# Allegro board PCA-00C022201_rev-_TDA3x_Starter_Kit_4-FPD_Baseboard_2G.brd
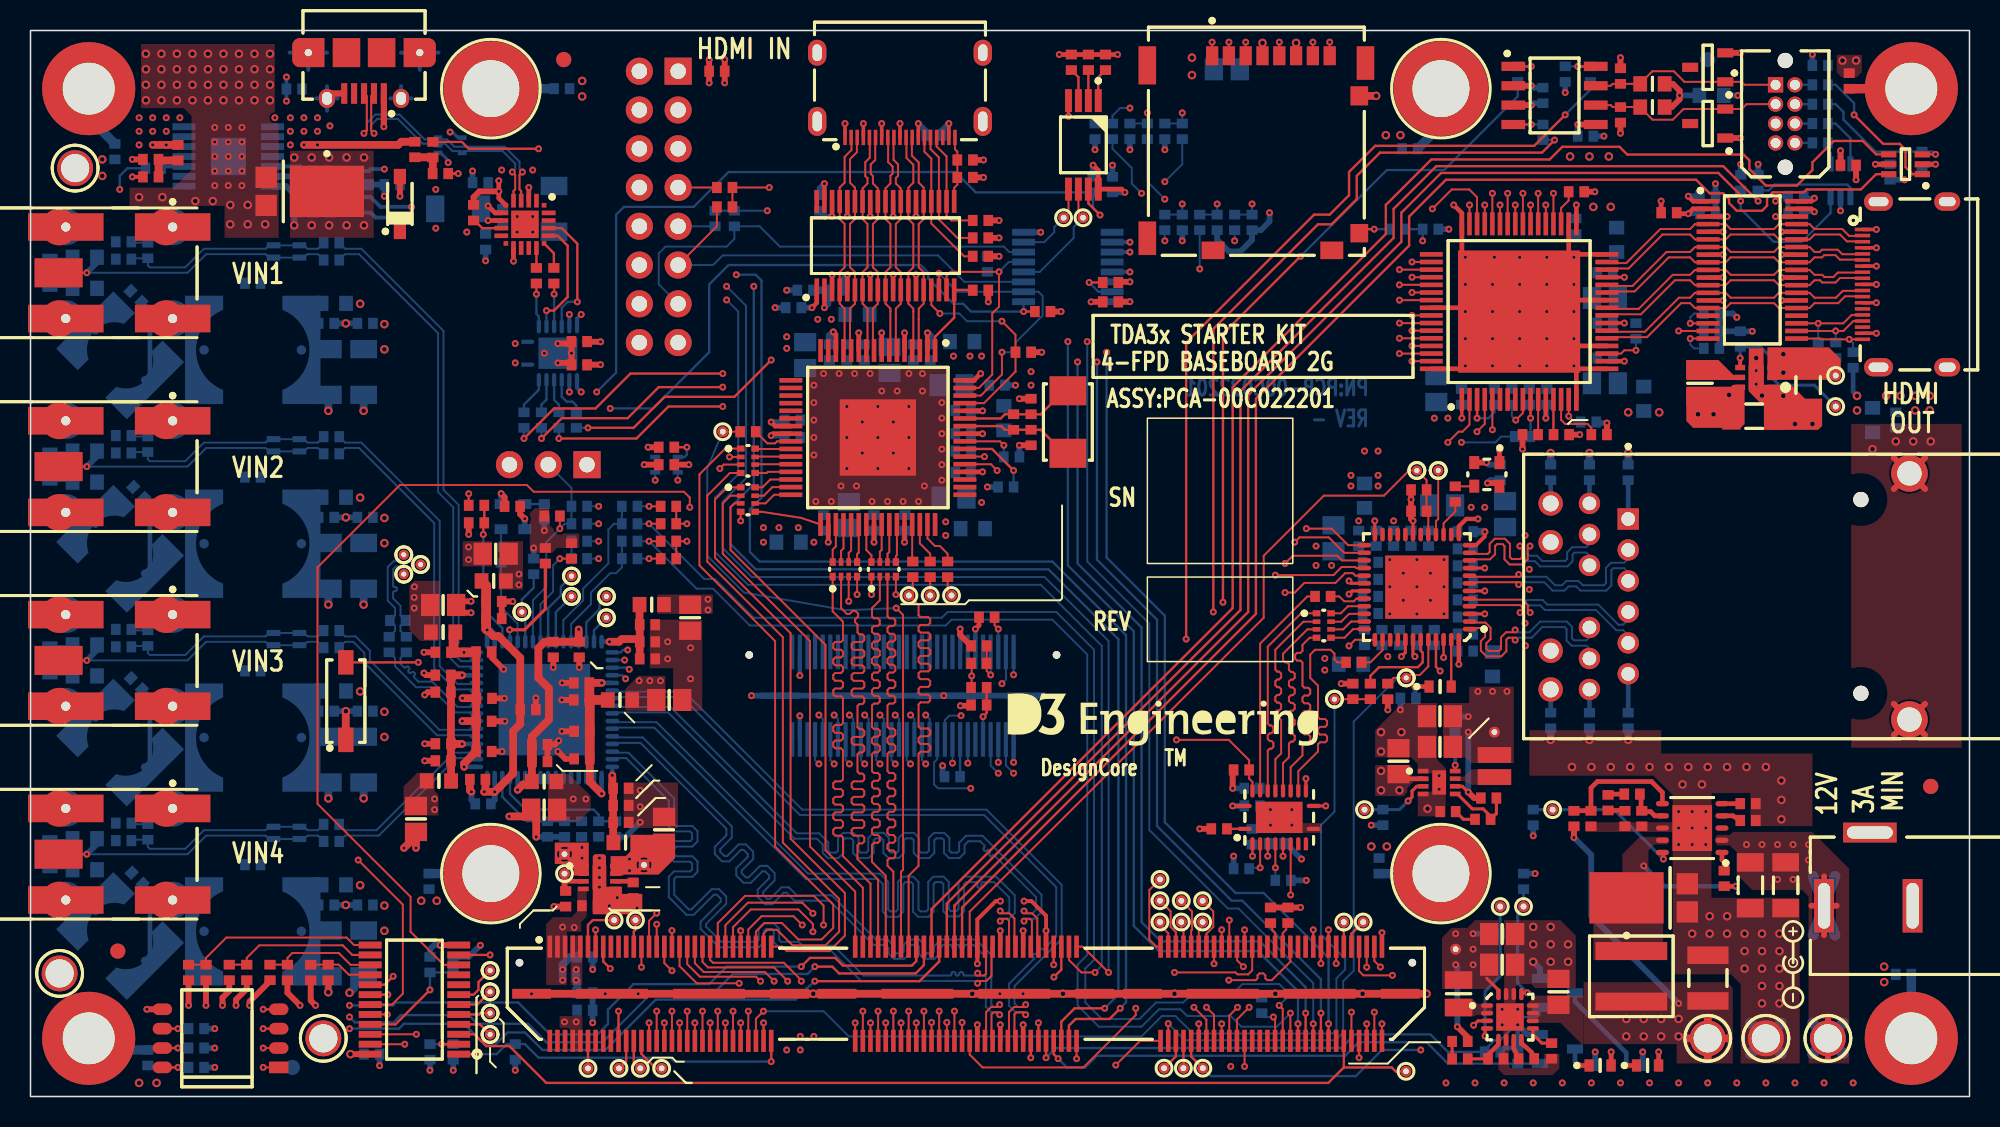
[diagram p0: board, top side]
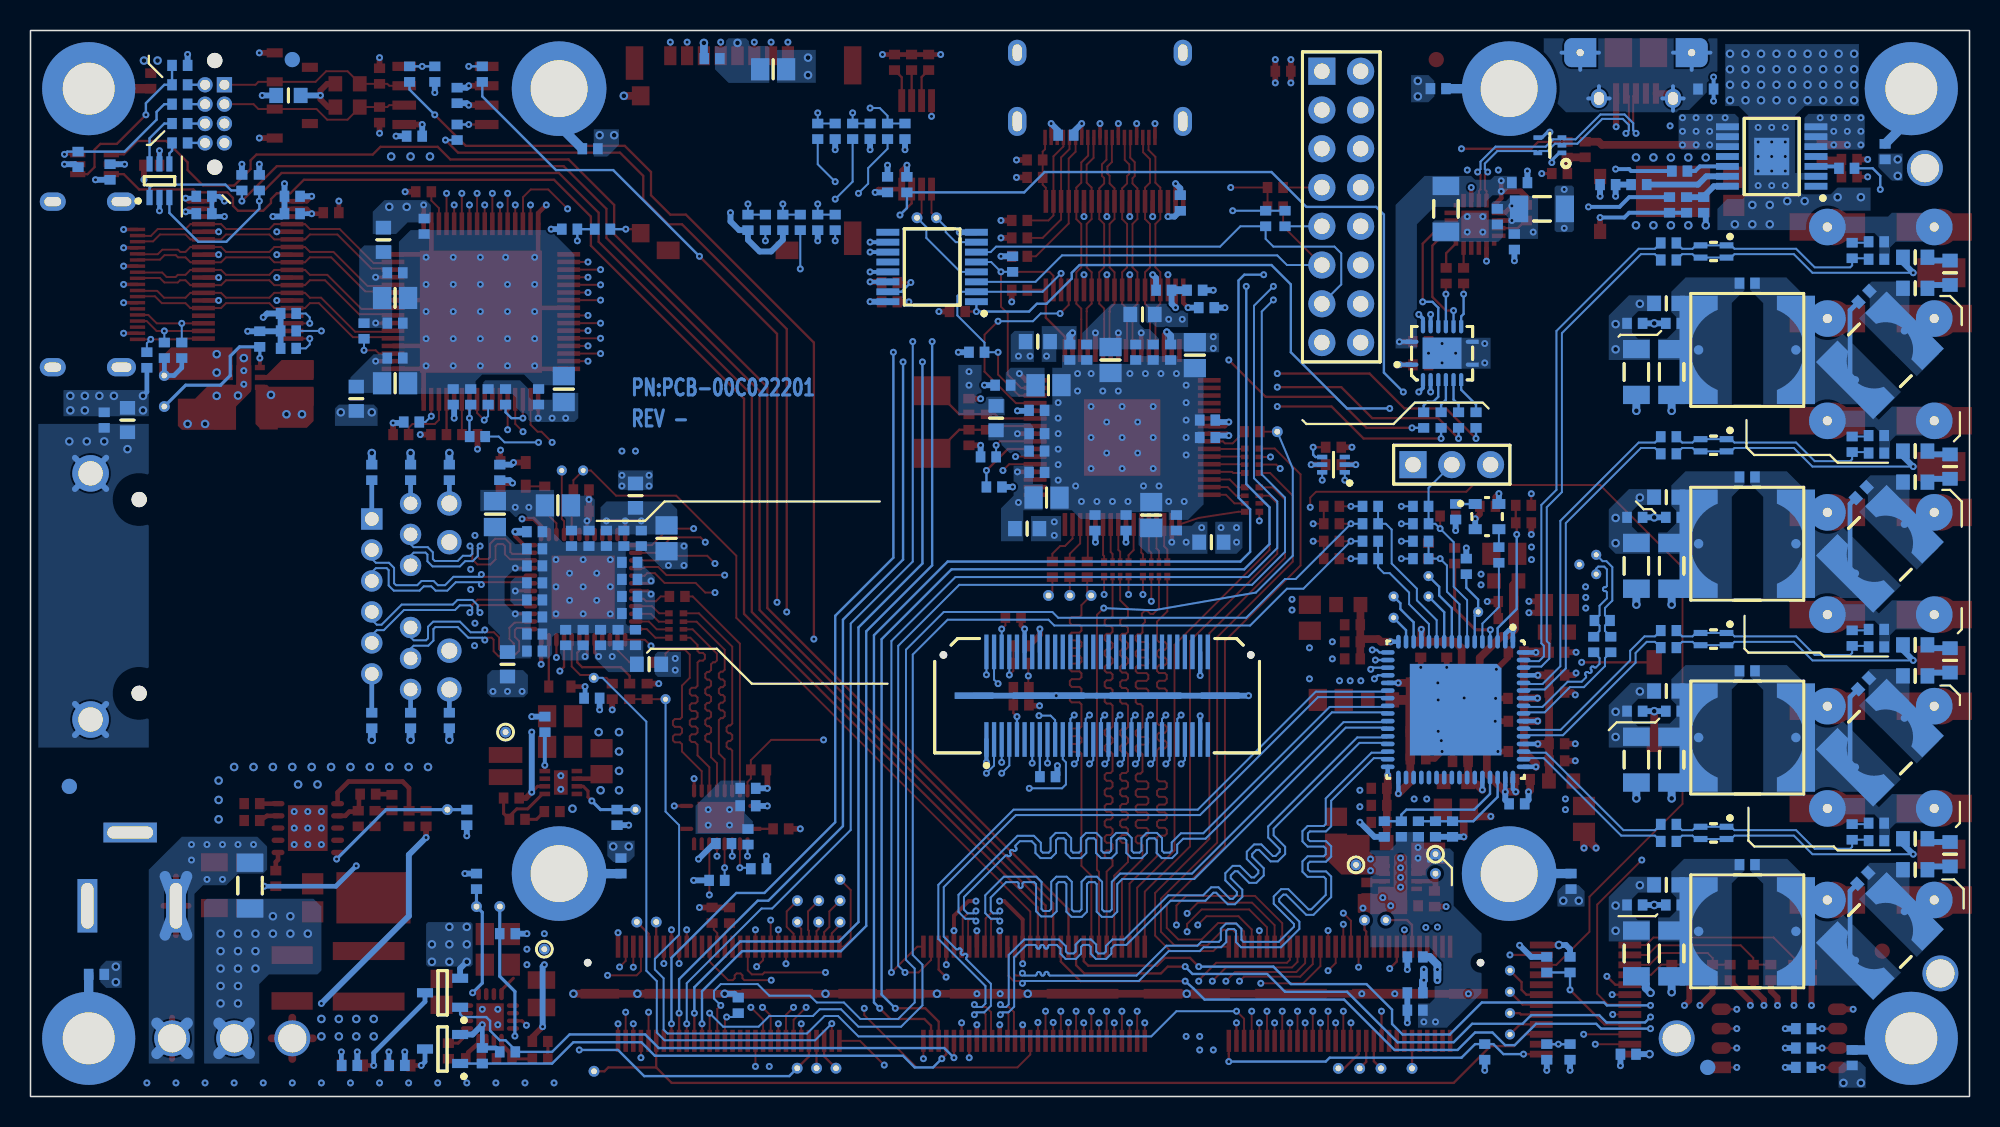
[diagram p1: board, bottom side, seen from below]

Outline 127 x 69.85 mm; copper layers: TOP, GND1, INNER1, GND2, PWR1, PWR2, GND3, INNER2, GND4, BOTTOM. Coordinates in mm from the lower left corner of the outline.
Outline path: rectangle 0,0 127,69.85

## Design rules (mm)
constraint set DEFAULT: min track width 0.152
net group CSI2_0_0: nets CSI2_0_DX0 CSI2_0_DY0
net group CSI2_0_1: nets CSI2_0_DX1 CSI2_0_DY1
net group CSI2_0_2: nets CSI2_0_DX2 CSI2_0_DY2
net group CSI2_0_3: nets CSI2_0_DX3 CSI2_0_DY3
net group CSI2_0_4: nets CSI2_0_DX4 CSI2_0_DY4
net group DCAN1: nets DCAN1_H DCAN1_L
net group HDMI_IN_CLK: nets HDMI_IN_CLKN HDMI_IN_CLKP
net group HDMI_IN_D0: nets HDMI_IN_D0N HDMI_IN_D0P
net group HDMI_IN_D1: nets HDMI_IN_D1N HDMI_IN_D1P
net group HDMI_IN_D2: nets HDMI_IN_D2N HDMI_IN_D2P
net group LPTX: nets LPTXN LPTXP
net group LPTX_C: nets LPTX_C_N LPTX_C_P
net group RIN0: nets RIN0_N RIN0_P
net group RIN0_C: nets RIN0_C_N RIN0_C_P
net group RIN1: nets RIN1_N RIN1_P
net group RIN1_C: nets RIN1_C_N RIN1_C_P
net group RIN2: nets RIN2_N RIN2_P
net group RIN2_C: nets RIN2_C_N RIN2_C_P
net group RIN3: nets RIN3_N RIN3_P
net group RIN3_C: nets RIN3_C_N RIN3_C_P
net group TD_A: nets TD_A_N TD_A_P
net group TD_B: nets TD_B_N TD_B_P
net group TD_C: nets TD_C_N TD_C_P
net group TD_D: nets TD_D_N TD_D_P
net group TXC: nets TXC_N TXC_P
net group TXD0: nets TXD0_N TXD0_P
net group TXD1: nets TXD1_N TXD1_P
net group TXD2: nets TXD2_N TXD2_P
net group USB_D: nets USB_DM USB_DP

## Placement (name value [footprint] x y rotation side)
C1  0.1uF  [CAPCEIA0402]  110.93 14.29 270 top
C2  10uF  [CAPCEIA1206]  112.65 13.84 270 top
C3  47uF  [CAPCEIA1210]  109.87 7.76 90 top
C5  2700pF  [CAPCEIA0402]  112.5 18.08 0 top
C6  12pF  [CAPCEIA0402]  105.54 18.21 270 top
C7  2700pF  [CAPCEIA0402]  104.43 18.21 270 top
C20  4.7uF  [CAPCEIA1206]  116.43 46.61 270 top
C21  4.7uF  [CAPCEIA1206]  112.9 44.58 0 top
C22  0.01uF  [CAPCEIA0402]  97.98 2.48 180 top
C23  10uF  [CAPCEIA0805]  96.39 8.64 0 top
C24  10uF  [CAPCEIA0805]  96.39 10.64 0 top
C25  0.082uF  [CAPCEIA0402]  99.63 2.98 90 top
C26  10uF  [CAPCEIA0805]  41.49 17.48 90 top
C27  1uF  [CAPCEIA0402]  38.67 17.96 0 top
C28  0.1uF  [CAPCEIA0402]  38.67 19.08 0 top
C29  0.01uF  [CAPCEIA0402]  38.67 20.19 180 top
C30  10uF  [CAPCEIA0805]  33.64 18.8 180 top
C31  1uF  [CAPCEIA0402]  34.24 29.29 270 top
C32  0.1uF  [CAPCEIA0402]  33.35 23.06 0 top
C33  0.01uF  [CAPCEIA0402]  33.35 21.95 180 top
C34  0.01uF  [CAPCEIA0402]  35.94 29.29 90 top
C35  10uF  [CAPCEIA0805]  27.03 32.21 0 top
C36  1uF  [CAPCEIA0402]  27.03 29.11 180 top
C37  0.1uF  [CAPCEIA0402]  29.69 29.13 0 top
C38  0.01uF  [CAPCEIA0402]  29.69 22.61 180 top
C39  0.01uF  [CAPCEIA0402]  29.69 24.59 180 top
C40  0.01uF  [CAPCEIA0402]  29.72 26.09 180 top
C41  10uF  [CAPCEIA0805]  41.83 25.98 0 top
C42  1uF  [CAPCEIA0402]  36.12 23.93 180 top
C43  0.1uF  [CAPCEIA0402]  36.09 27.1 180 top
C44  0.01uF  [CAPCEIA0402]  36.09 25.98 0 top
C45  0.01uF  [CAPCEIA0402]  36.12 22.12 0 top
C46  10uF  [CAPCEIA0805]  30.47 35.56 180 top
C47  1uF  [CAPCEIA0402]  32.59 25.35 0 top
C48  0.1uF  [CAPCEIA0402]  30.35 31.32 0 top
C49  0.01uF  [CAPCEIA0402]  30.35 32.44 180 top
C50  0.01uF  [CAPCEIA0402]  29.29 20.78 0 top
C51  0.01uF  [CAPCEIA0402]  29.64 19.18 0 bottom
C52  10uF  [CAPCEIA0805]  25.25 18.19 270 top
C53  1uF  [CAPCEIA0402]  27.03 22 180 top
C54  0.1uF  [CAPCEIA0402]  27.03 26.49 180 top
C55  0.01uF  [CAPCEIA0402]  27.03 23.11 0 top
C56  0.01uF  [CAPCEIA0402]  27.03 27.61 0 top
C57  10uF  [CAPCEIA0805]  43.21 31.37 270 top
C58  1uF  [CAPCEIA0402]  40.41 29.79 0 top
C59  0.1uF  [CAPCEIA0402]  40.41 30.91 0 top
C60  0.01uF  [CAPCEIA0402]  40.41 28.68 180 top
C61  NP  [CAPCEIA0402]  23.5 29.62 90 bottom
C62  NP  [CAPCEIA0402]  24.61 29.62 90 bottom
C63  0.1uF  [CAPCEIA0402]  33.86 17.53 270 bottom
C65  0.1uF  [CAPCEIA0402]  19.38 12.55 180 bottom
C66  4.7uF  [CAPCEIA1206]  19.51 9.37 270 bottom
C67  0.1uF  [CAPCEIA0402]  21.92 12.55 0 bottom
C68  4.7uF  [CAPCEIA1206]  21.82 9.37 270 bottom
C69  0.1uF  [CAPCEIA0402]  19.38 25.25 180 bottom
C70  4.7uF  [CAPCEIA1206]  19.51 22.07 270 bottom
C71  0.1uF  [CAPCEIA0402]  21.92 25.25 0 bottom
C72  4.7uF  [CAPCEIA1206]  21.82 22.07 270 bottom
C73  0.1uF  [CAPCEIA0402]  19.71 16.71 0 bottom
C74  0.1uF  [CAPCEIA0402]  19.71 29.41 0 bottom
C75  0.047uF  [CAPCEIA0402]  19.71 17.83 0 bottom
C76  0.047uF  [CAPCEIA0402]  19.71 30.53 0 bottom
C77  NP  [CAPCEIA0402]  7.68 17.34 270 bottom
C78  NP  [CAPCEIA0402]  7.68 30.04 270 bottom
C79  0.1uF  [CAPCEIA0402]  19.38 37.95 180 bottom
C80  4.7uF  [CAPCEIA1206]  19.51 34.77 270 bottom
C81  0.1uF  [CAPCEIA0402]  21.92 37.95 0 bottom
C82  4.7uF  [CAPCEIA1206]  21.82 34.77 270 bottom
C83  0.1uF  [CAPCEIA0402]  19.38 50.66 180 bottom
C84  4.7uF  [CAPCEIA1206]  19.51 47.47 270 bottom
C85  0.1uF  [CAPCEIA0402]  21.92 50.66 0 bottom
C86  4.7uF  [CAPCEIA1206]  21.82 47.47 270 bottom
C87  0.1uF  [CAPCEIA0402]  19.71 42.11 0 bottom
C88  0.1uF  [CAPCEIA0402]  19.71 54.81 0 bottom
C89  0.047uF  [CAPCEIA0402]  19.71 43.23 0 bottom
C90  0.047uF  [CAPCEIA0402]  19.71 55.93 0 bottom
C91  NP  [CAPCEIA0402]  7.68 42.74 270 bottom
C92  NP  [CAPCEIA0402]  7.68 55.44 270 bottom
C107  56pF  [CAPCEIA0402]  104.14 66.87 90 top
C108  56pF  [CAPCEIA0402]  104.14 64.33 270 top
C109  1uF  [CAPCEIA0402]  99.06 65.6 90 bottom
C110  1uF  [CAPCEIA0402]  101.85 62.93 0 bottom
C111  NP  [CAPCEIA0603]  110.11 65.6 0 bottom
C123  0.1uF  [CAPCEIA0402]  31.56 38.67 0 top
C124  10uF  [CAPCEIA0805]  89.6 21.97 90 top
C125  10uF  [CAPCEIA0805]  92.32 22.91 180 top
C126  10uF  [CAPCEIA0805]  92.32 24.92 180 top
C127  1uF  [CAPCEIA0402]  88.14 36.58 270 bottom
C128  1uF  [CAPCEIA0402]  87.76 31.65 0 bottom
C129  1uF  [CAPCEIA0402]  91.95 30.07 90 bottom
C130  1uF  [CAPCEIA0402]  93.98 32.54 180 bottom
C131  1uF  [CAPCEIA0402]  93.98 35.89 180 bottom
C132  1uF  [CAPCEIA0402]  93.98 30.3 180 bottom
C135  1uF  [CAPCEIA0402]  91.57 36.58 270 bottom
C136  1uF  [CAPCEIA0402]  87.76 35 0 bottom
C137  1uF  [CAPCEIA0402]  88.52 30.07 90 bottom
C140  0.01uF  [CAPCEIA0402]  96.27 40.89 90 bottom
C141  0.1uF  [CAPCEIA0402]  90.42 36.58 270 bottom
C142  0.1uF  [CAPCEIA0402]  93.98 34.77 180 bottom
C143  0.1uF  [CAPCEIA0402]  89.28 36.58 270 bottom
C144  10uF  [CAPCEIA0805]  92.46 38.73 0 bottom
C145  10uF  [CAPCEIA0805]  96.58 38.16 90 bottom
C146  10uF  [CAPCEIA0805]  85.34 36.58 270 bottom
C150  0.1uF  [CAPCEIA0402]  102.11 24.64 270 bottom
C151  0.1uF  [CAPCEIA0402]  104.65 24.64 270 bottom
C152  0.1uF  [CAPCEIA0402]  104.65 40.89 90 bottom
C153  0.1uF  [CAPCEIA0402]  102.11 40.89 90 bottom
C155  0.1uF  [CAPCEIA0402]  122.17 44.32 270 bottom
C156  10uF  [CAPCEIA0805]  100.08 6.86 90 top
C157  0.1uF  [CAPCEIA0402]  103.12 53.98 180 bottom
C158  0.1uF  [CAPCEIA0402]  103.12 50.67 180 bottom
C159  0.1uF  [CAPCEIA0402]  103.12 48.39 180 bottom
C160  0.1uF  [CAPCEIA0402]  99.31 45.85 90 bottom
C161  0.1uF  [CAPCEIA0402]  93.73 45.85 90 bottom
C162  0.1uF  [CAPCEIA0402]  101.22 57.02 270 bottom
C163  10uF  [CAPCEIA0805]  103.12 52.32 180 bottom
C164  10uF  [CAPCEIA0805]  103.12 46.74 180 bottom
C165  10uF  [CAPCEIA0805]  92.08 46.35 90 bottom
C166  0.1uF  [CAPCEIA0402]  115.63 58.99 180 bottom
C167  10uF  [CAPCEIA0805]  78.36 67.31 180 bottom
C168  0.1uF  [CAPCEIA0402]  82.36 68.01 0 bottom
C175  0.1uF  [CAPCEIA0402]  109.86 58.99 0 bottom
C176  0.1uF  [CAPCEIA0402]  115.63 57.85 180 bottom
C177  0.1uF  [CAPCEIA0402]  109.86 57.85 0 bottom
C178  1uF  [CAPCEIA0402]  36.63 12.5 0 top
C179  NP  [CAPCEIA0402]  39.47 13.51 270 top
C180  0.1uF  [CAPCEIA0402]  22.35 2.77 0 bottom
C181  0.1uF  [CAPCEIA0402]  41.66 41.4 180 top
C182  1uF  [CAPCEIA0402]  36.31 6.79 0 bottom
C183  1uF  [CAPCEIA0402]  36.31 9.14 0 bottom
C184  1uF  [CAPCEIA0402]  36.31 5.65 0 bottom
C186  1uF  [CAPCEIA0402]  80.01 20.19 0 bottom
C187  0.01uF  [CAPCEIA0402]  80.01 19.05 0 bottom
C191  0.1uF  [CAPCEIA0402]  29.81 56.01 270 bottom
C192  0.1uF  [CAPCEIA0402]  30.92 57.66 270 bottom
C193  4.7uF  [CAPCEIA1206]  34.29 58.17 270 bottom
C194  0.1uF  [CAPCEIA0402]  29.46 59.88 180 bottom
C207  0.1uF  [CAPCEIA0402]  35.94 47.94 180 top
C208  0.1uF  [CAPCEIA0402]  35.94 49.47 180 top
C213  4.7uF  [CAPCEIA1206]  28 58.17 180 bottom
C217  0.1uF  [CAPCEIA0402]  121.79 60.58 270 bottom
C218  0.1uF  [CAPCEIA0402]  119.06 61.02 0 top
C220  0.1uF  [CAPCEIA0402]  59.18 62.99 180 bottom
C221  0.1uF  [CAPCEIA0402]  51.69 58.55 270 bottom
C222  0.1uF  [CAPCEIA0402]  49.97 51.69 180 bottom
C223  0.1uF  [CAPCEIA0402]  52.77 52.83 0 bottom
C224  10uF  [CAPCEIA0805]  60.33 46.61 180 bottom
C229  10uF  [CAPCEIA0805]  53.59 38.1 90 bottom
C230  0.1uF  [CAPCEIA0402]  57.28 37.59 90 bottom
C231  0.1uF  [CAPCEIA0402]  51.94 37.59 90 bottom
C232  0.1uF  [CAPCEIA0402]  49.91 44.32 0 bottom
C235  0.1uF  [CAPCEIA0402]  57.82 48.77 270 bottom
C236  0.1uF  [CAPCEIA0402]  54.61 48.77 270 bottom
C237  0.1uF  [CAPCEIA0402]  53.47 48.77 270 bottom
C238  10uF  [CAPCEIA0805]  56.26 48.26 270 bottom
C239  0.1uF  [CAPCEIA0402]  61.09 44.96 180 bottom
C240  0.1uF  [CAPCEIA0402]  61.09 40.89 180 bottom
C241  0.1uF  [CAPCEIA0402]  49.91 43.18 0 bottom
C242  0.1uF  [CAPCEIA0402]  55.24 37.59 90 bottom
C243  10uF  [CAPCEIA0805]  60.45 39.24 180 bottom
C246  0.1uF  [CAPCEIA0402]  52.32 48.77 270 bottom
C247  0.1uF  [CAPCEIA0402]  58.93 48.77 270 bottom
C248  10uF  [CAPCEIA0805]  50.74 48.58 270 bottom
C250  0.1uF  [CAPCEIA0402]  61.09 42.29 180 bottom
C251  0.01uF  [CAPCEIA0402]  61.09 43.43 180 bottom
C252  27pF  [CAPCEIA0402]  65.53 43.18 270 top
C253  27pF  [CAPCEIA0402]  65.53 45.21 90 top
C254  0.1uF  [CAPCEIA0402]  93.98 31.42 180 bottom
C255  0.1uF  [CAPCEIA0402]  87.76 32.77 0 bottom
C256  0.1uF  [CAPCEIA0402]  90.81 30.07 90 bottom
C257  0.1uF  [CAPCEIA0402]  93.98 33.66 180 bottom
C258  0.1uF  [CAPCEIA0402]  87.76 33.88 0 bottom
C259  0.1uF  [CAPCEIA0402]  89.66 30.07 90 bottom
C260  0.01uF  [CAPCEIA0402]  87 36.58 270 bottom
C261  0.01uF  [CAPCEIA0402]  87.38 30.07 90 bottom
C262  0.01uF  [CAPCEIA0402]  93.98 29.18 180 bottom
C263  0.1uF  [CAPCEIA0402]  44.96 67.18 0 top
C264  0.1uF  [CAPCEIA0402]  70.87 59.75 90 bottom
C265  0.1uF  [CAPCEIA0402]  70.74 52.07 180 top
C266  10uF  [CAPCEIA1206]  114.96 13.84 270 top
C267  10uF  [CAPCEIA1206]  112.62 13.82 270 bottom
D1  PDS760Q-13  [DIO_DIODES_PDS760Q]  105.66 13.02 90 top
D8  MMBZ27VCLT1G  [SOT95P237X111-3N]  109.86 63.75 180 top
D9  MMBZ27VCLT1G  [SOT95P237X111-3N]  109.86 67.44 180 top
D12  GREEN  [LEDC1608X65N]  92.33 26.86 0 top
D17  GREEN  [LEDC1608X65N]  105.92 2.03 0 top
D18  GREEN  [LEDC1608X65N]  102.81 2.03 0 top
D21  MMSZ4678T1G  [SOD3716X135N]  24.19 58.48 90 top
D23  PDS760Q-13  [DIO_DIODES_PDS760Q]  18.29 59.31 270 top
J6  59S2AQ-40MT5-Z_1  [ROSENBERGER_59S2AQ-40MT5-Y_1]  5.81 15.88 270 top
J7  59S2AQ-40MT5-Z_1  [ROSENBERGER_59S2AQ-40MT5-Y_1]  5.81 28.57 270 top
J8  59S2AQ-40MT5-Z_1  [ROSENBERGER_59S2AQ-40MT5-Y_1]  5.81 41.27 270 top
J9  59S2AQ-40MT5-Z_1  [ROSENBERGER_59S2AQ-40MT5-Y_1]  5.81 53.98 270 top
J13  QSH-030  [SAMTEC_QSH-030-01-L-D-A-K]  64.39 23.39 180 bottom
J14  QTH-090-02  [SAMTEC_QTH-090-02-L-D-A-K]  34.01 9.82 0 top
J19  685119136923  [WURTH_685119136923]  119.99 56.81 270 top
J21  503182-1853  [MOLEX_5031821853]  77.39 68.2 0 top
J23  MicroUSB-B  [HIROSE_ZX62D-B-5P8]  23.14 65.73 180 top
J24  RJ-45 (JK0-0136NL)  [JACK_PULSE_JK0-0136NL]  104.65 32.77 180 top
J25  Power Jack  [WURTH_694106301002]  117.47 12.5 180 top
J26  685119136923  [WURTH_685119136923]  53.35 62.84 0 top
J27  NP-HEADER8x2  [D3-ST_HEADER_8X2_100]  42.42 67.18 270 bottom
J28  Samtec TFC-104-01  [SAMTEC_TFC-104-01-F-D-A]  114.3 66.29 270 top
J29  NP-Thru-Hole3x1  [MOLEX_22-28-4033]  36.45 41.4 180 bottom
L1  6.8uH  [DFN528X548X510-2N]  104.85 7.87 270 top
L2  1.0uH  [INDC2016X180N]  109.35 46.74 90 top
L3  1.0uH  [INDC2016X180N]  93.54 6.73 90 top
L4  120 Ohm @ 100MHz  [INDCEIA0603]  38.98 16.64 180 top
L5  120 Ohm @ 100MHz  [INDCEIA0603]  33.64 20.64 180 top
L6  120 Ohm @ 100MHz  [INDCEIA0603]  27.03 30.43 0 top
L7  120 Ohm @ 100MHz  [INDCEIA0603]  38.61 25.98 180 top
L8  120 Ohm @ 100MHz  [INDCEIA0603]  30.34 33.78 180 top
L9  120 Ohm @ 100MHz  [INDCEIA0603]  26.75 20.68 0 top
L10  120 Ohm @ 100MHz  [INDCEIA0603]  40.69 32.23 180 top
L11  1000 Ohm @ 100MHz  [INDCEIA0603]  19.86 13.87 0 bottom
L12  1000 Ohm @ 100MHz  [INDCEIA0603]  19.86 26.57 0 bottom
L13  4.7uH  [IND_WURTH_WE-TPC-4818]  5.87 10.52 315 bottom
L14  100uH  [IND_COILCRAFT_MSS7341T]  14.55 10.82 0 bottom
L15  4.7uH  [IND_WURTH_WE-TPC-4818]  5.87 23.19 315 bottom
L16  100uH  [IND_COILCRAFT_MSS7341T]  14.55 23.52 0 bottom
L17  1000 Ohm @ 100MHz  [INDCEIA0603]  3.56 16.89 0 bottom
L18  1000 Ohm @ 100MHz  [INDCEIA0603]  3.56 29.59 0 bottom
L19  NP  [IND_MURATA_DLW21SN900HQ2L]  16.76 17.27 0 bottom
L20  NP  [IND_MURATA_DLW21SN900HQ2L]  16.76 29.97 0 bottom
L21  1000 Ohm @ 100MHz  [INDCEIA0603]  19.86 39.27 0 bottom
L22  1000 Ohm @ 100MHz  [INDCEIA0603]  19.86 51.97 0 bottom
L23  4.7uH  [IND_WURTH_WE-TPC-4818]  5.87 35.89 315 bottom
L24  100uH  [IND_COILCRAFT_MSS7341T]  14.55 36.22 0 bottom
L25  4.7uH  [IND_WURTH_WE-TPC-4818]  5.87 48.56 315 bottom
L26  100uH  [IND_COILCRAFT_MSS7341T]  14.55 48.92 0 bottom
L27  1000 Ohm @ 100MHz  [INDCEIA0603]  3.56 42.29 0 bottom
L28  1000 Ohm @ 100MHz  [INDCEIA0603]  3.56 54.99 0 bottom
L29  NP  [IND_MURATA_DLW21SN900HQ2L]  16.76 42.67 0 bottom
L30  NP  [IND_MURATA_DLW21SN900HQ2L]  16.76 55.37 0 bottom
L36  2.2uH  [IND_COILCRAFT_XPL2010]  95.89 21.65 90 top
L37  120 Ohm @ 100MHz  [INDCEIA0603]  87.38 39.37 270 bottom
L38  120 Ohm @ 100MHz  [INDCEIA0603]  95.76 28.32 90 bottom
L40  120 Ohm @ 100MHz  [INDCEIA0603]  86.49 28.32 0 bottom
L41  120 Ohm @ 100MHz  [INDCEIA0603]  120.65 44.32 270 bottom
L42  1000ohm  [INDCEIA0603]  103.89 56.13 270 bottom
L43  1000ohm  [INDCEIA0603]  105.66 45.72 270 bottom
L47  120 Ohm @ 100MHz  [INDCEIA0603]  49.66 36.32 0 bottom
L48  120 Ohm @ 100MHz  [INDCEIA0603]  54.17 51.24 0 bottom
L49  120 Ohm @ 100MHz  [INDCEIA0603]  61.72 37.21 0 bottom
L50  120 Ohm @ 100MHz  [INDCEIA0603]  61.02 49.47 180 bottom
L51  120 Ohm @ 100MHz  [INDCEIA0603]  63.75 44.45 270 bottom
LR1  0.0  [RESCEIA0603]  1.27 15.88 90 bottom
LR2  0.0  [RESCEIA0603]  1.27 28.57 90 bottom
LR3  0.0  [RESCEIA0603]  1.27 41.27 90 bottom
LR4  0.0  [RESCEIA0603]  1.27 53.98 90 bottom
LR5  0.0  [RESCEIA0603]  3.56 14.86 180 bottom
LR6  0.0  [RESCEIA0603]  3.56 27.56 180 bottom
LR7  0.0  [RESCEIA0603]  3.56 40.26 180 bottom
LR8  0.0  [RESCEIA0603]  3.56 52.96 180 bottom
MH1  MOUNT HOLE  [MTG340_610]  123.19 3.81 180 top
MH2  MOUNT HOLE  [MTG340_610]  3.81 3.81 180 top
MH3  MOUNT HOLE  [MTG340_610]  123.19 66.04 180 top
MH4  MOUNT HOLE  [MTG340_610]  3.81 66.04 180 top
MH5  SMTSO-M2-8ET  [PENN_SMTSO-M2-8ET]  92.38 14.61 180 top
MH6  SMTSO-M2-8ET  [PENN_SMTSO-M2-8ET]  30.15 14.61 180 top
MH7  SMTSO-M2-8ET  [PENN_SMTSO-M2-8ET]  92.38 66.04 180 top
MH8  SMTSO-M2-8ET  [PENN_SMTSO-M2-8ET]  30.15 66.04 180 top
NOREF  -  []  -28.73 -59.05 0 top
NOREF#2  -  []  64.01 22.99 0 top
NOREF#3  -  [unnamed#2]  5.71 9.53 0 top
NOREF#4  -  [unnamed#2]  34.92 67.94 0 top
NOREF#5  -  []  64.01 22.99 0 top
NOREF#6  -  []  0 0 0 top
NOREF#7  -  [unnamed#2]  124.46 20.32 0 top
NOREF#8  -  []  -19.68 -43.56 0 top
NOREF#9  -  []  127 0 90 top
NOREF#10  -  [unnamed#2]  109.86 67.94 180 bottom
NOREF#11  -  [unnamed#2]  124.46 20.32 180 bottom
NOREF#12  -  [unnamed#2]  17.14 1.91 180 bottom
Q7  2N7002L  [SOT95P237X111-3N]  100.01 3.11 0 bottom
Q8  2N7002L  [SOT95P237X111-3N]  100.01 6.79 0 bottom
R8  10K_1%  [RESCEIA0402]  98.42 18.29 90 bottom
R10  31.6K_1%  [RESCEIA0402]  101.09 18.21 90 top
R12  11.0K_1%  [RESCEIA0402]  104.9 19.81 180 top
R13  118K_1%  [RESCEIA0402]  112.5 19.19 0 top
R14  10K_1%  [RESCEIA0402]  102.21 18.21 270 top
R24  4.02K_1%  [RESCEIA0402]  8.04 60.82 0 bottom
R25  4.02K_1%  [RESCEIA0402]  18.99 60.64 180 bottom
R26  4.02K_1%  [RESCEIA0402]  18.53 58.42 90 bottom
R28  510_1%  [RESCEIA0402]  17.41 58.42 270 bottom
R30  1K_1%  [RESCEIA0402]  21.65 59.75 0 bottom
R31  1K_1%  [RESCEIA0402]  23.69 59.75 0 bottom
R33  11.0K_1%  [RESCEIA0402]  93.62 3.61 180 top
R34  100K_1%  [RESCEIA0402]  95.76 10.67 180 bottom
R35  100K_1%  [RESCEIA0402]  95.97 2.48 0 top
R36  0.0  [RESCEIA0402]  39.24 37.53 0 bottom
R37  NP  [RESCEIA0402]  39.24 38.67 0 bottom
R38  0.0  [RESCEIA0402]  39.24 36.39 0 bottom
R39  NP  [RESCEIA0402]  39.24 35.24 0 bottom
R40  NP  [RESCEIA0402]  35.94 37.53 0 bottom
R41  NP  [RESCEIA0402]  35.94 38.67 0 bottom
R42  4.02K_1%  [RESCEIA0402]  32.96 34.73 270 bottom
R43  NP  [RESCEIA0402]  35.94 36.39 0 bottom
R44  NP  [RESCEIA0402]  35.94 35.24 0 bottom
R45  0.0  [RESCEIA0402]  30.82 35.48 270 bottom
R46  NP  [RESCEIA0402]  24.05 31.19 0 bottom
R51  118K_1%  [RESCEIA0402]  36.09 17.53 90 bottom
R53  31.6K_1%  [RESCEIA0402]  34.98 17.53 270 bottom
R58  80.6K_1%  [RESCEIA0402]  37.21 17.53 90 bottom
R59  1K_1%  [RESCEIA0402]  33.66 38.32 90 bottom
R60  100K_1%  [RESCEIA0402]  33.72 35.43 270 top
R61  100K_1%  [RESCEIA0402]  38.33 17.53 270 bottom
R63  1K_1%  [RESCEIA0402]  6.99 14.3 315 bottom
R64  1K_1%  [RESCEIA0402]  14.55 15.19 0 bottom
R65  1K_1%  [RESCEIA0402]  6.93 27.05 315 bottom
R66  1K_1%  [RESCEIA0402]  14.55 27.89 0 bottom
R67  49.9_1%  [RESCEIA0402]  6.1 16.76 0 bottom
R68  49.9_1%  [RESCEIA0402]  6.1 29.46 0 bottom
R69  NP  [RESCEIA0402]  6.1 17.91 0 bottom
R70  NP  [RESCEIA0402]  6.1 30.61 0 bottom
R71  1K_1%  [RESCEIA0402]  7.09 39.57 315 bottom
R72  1K_1%  [RESCEIA0402]  14.55 40.59 0 bottom
R73  1K_1%  [RESCEIA0402]  6.91 52.43 315 bottom
R74  1K_1%  [RESCEIA0402]  14.55 53.29 0 bottom
R75  49.9_1%  [RESCEIA0402]  6.1 42.16 0 bottom
R76  49.9_1%  [RESCEIA0402]  6.1 54.86 0 bottom
R77  NP  [RESCEIA0402]  6.1 43.31 0 bottom
R78  NP  [RESCEIA0402]  6.1 56.01 0 bottom
R89  0.0  [RESCEIA0402]  102.17 66.99 90 bottom
R90  0.0  [RESCEIA0402]  97.41 66.99 90 bottom
R91  0.0  [RESCEIA0402]  99.06 63.18 90 bottom
R92  62.0_1%  [RESCEIA0603]  106.24 66.36 0 top
R93  62.0_1%  [RESCEIA0603]  106.24 64.83 0 top
R101  NP  [RESCEIA0402]  32.32 44.32 270 bottom
R102  0.0  [RESCEIA0402]  33.46 44.32 270 bottom
R104  NP  [RESCEIA0402]  34.61 44.32 270 bottom
R105  0.0  [RESCEIA0402]  35.75 44.32 270 bottom
R107  4.02K_1%  [RESCEIA0402]  62.12 25.65 0 top
R108  4.02K_1%  [RESCEIA0402]  62.64 31.4 0 top
R109  0.0  [RESCEIA0402]  62.12 28.38 180 top
R110  NP  [RESCEIA0402]  62.12 26.8 180 top
R111  NP  [RESCEIA0402]  62.12 29.53 180 top
R112  0.0  [RESCEIA0402]  60.38 20.95 0 bottom
R117  11.0K_1%  [RESCEIA0402]  93.98 37.01 180 bottom
R118  100K_1%  [RESCEIA0402]  93.31 24.38 90 bottom
R119  80.6K_1%  [RESCEIA0402]  95.12 18.16 180 top
R120  383K_1%  [RESCEIA0402]  95.5 19.56 0 top
R121  4.02K_1%  [RESCEIA0402]  88.9 26.54 90 top
R125  4.02K_1%  [RESCEIA0402]  90.93 39.75 0 top
R130  100K_1%  [RESCEIA0402]  98.17 45.85 90 bottom
R131  0.0  [RESCEIA0402]  95.89 45.85 90 bottom
R132  100K_1%  [RESCEIA0402]  102.04 44.2 180 bottom
R133  100K_1%  [RESCEIA0402]  102.74 43.37 180 top
R134  0.0  [RESCEIA0402]  97.73 43.24 180 bottom
R135  10K_1%  [RESCEIA0402]  100.27 43.37 0 top
R136  10K_1%  [RESCEIA0402]  97.03 45.85 270 bottom
R137  10K_1%  [RESCEIA0402]  101.26 59.28 180 top
R138  10K_1%  [RESCEIA0402]  98.23 43.37 0 top
R139  510_1%  [RESCEIA0402]  105.16 50.16 90 bottom
R145  49.9_1%  [RESCEIA0402]  70.87 63.25 90 bottom
R146  49.9_1%  [RESCEIA0402]  73.15 63.25 90 bottom
R147  49.9_1%  [RESCEIA0402]  75.44 63.25 90 bottom
R148  49.9_1%  [RESCEIA0402]  76.58 57.28 90 bottom
R149  49.9_1%  [RESCEIA0402]  78.87 57.28 90 bottom
R150  49.9_1%  [RESCEIA0402]  74.3 57.28 90 bottom
R151  1K_1%  [RESCEIA0402]  89.53 56.83 0 bottom
R152  10K_1%  [RESCEIA0402]  69.72 63.25 90 bottom
R153  10K_1%  [RESCEIA0402]  72.01 63.25 90 bottom
R154  10K_1%  [RESCEIA0402]  74.3 63.25 90 bottom
R155  10K_1%  [RESCEIA0402]  77.72 57.28 90 bottom
R156  10K_1%  [RESCEIA0402]  80.01 57.28 90 bottom
R157  10K_1%  [RESCEIA0402]  75.44 57.28 90 bottom
R158  47.0K_1%  [RESCEIA0402]  91.69 56.83 180 bottom
R166  10K_1%  [RESCEIA0402]  100.52 66.99 270 bottom
R172  10K_1%  [RESCEIA0402]  97.79 14.1 270 bottom
R174  22.0  [RESCEIA0402]  86.68 28.45 0 top
R179  22.0  [RESCEIA0402]  84.65 32.77 0 top
R180  0.0  [RESCEIA0402]  87.76 26.54 90 top
R181  200_1%  [RESCEIA0402]  90.23 26.1 180 bottom
R182  510_1%  [RESCEIA0402]  99.57 40.89 90 bottom
R183  510_1%  [RESCEIA0402]  99.57 24.64 270 bottom
R184  0.0  [RESCEIA0402]  35.05 12.95 90 top
R185  10K_1%  [RESCEIA0402]  10.35 8.13 90 top
R186  NP  [RESCEIA0402]  11.49 8.13 270 top
R187  NP  [RESCEIA0402]  14.16 8.13 270 top
R188  10K_1%  [RESCEIA0402]  13.02 8.13 90 top
R189  NP  [RESCEIA0402]  16.83 8.13 270 top
R190  10K_1%  [RESCEIA0402]  15.68 8.13 90 top
R191  10K_1%  [RESCEIA0402]  19.49 8.13 270 top
R192  NP  [RESCEIA0402]  18.35 8.13 90 top
R193  10K_1%  [RESCEIA0402]  26.16 2.92 270 bottom
R194  NP  [RESCEIA0402]  27.69 2.92 90 bottom
R195  10K_1%  [RESCEIA0402]  26.16 8.64 90 bottom
R196  NP  [RESCEIA0402]  27.69 8.64 270 bottom
R197  10K_1%  [RESCEIA0402]  31.75 2.92 90 bottom
R199  NP  [RESCEIA0402]  80.01 17.02 90 bottom
R200  NP  [RESCEIA0402]  82.36 11.87 270 top
R201  NP  [RESCEIA0402]  80.64 5.97 90 bottom
R202  NP  [RESCEIA0402]  81.22 11.87 270 top
R203  1K_1%  [RESCEIA0402]  10.86 1.91 0 bottom
R204  1K_1%  [RESCEIA0402]  10.86 3.17 180 bottom
R205  NP  [RESCEIA0402]  79.31 14.92 0 bottom
R206  NP  [RESCEIA0402]  81.6 16.57 180 bottom
R207  NP  [RESCEIA0402]  82.04 14.16 0 bottom
R222  0.0  [RESCEIA0402]  41.66 42.55 180 top
R223  NP  [RESCEIA0402]  122.68 8 180 bottom
R224  NP  [RESCEIA0402]  7.68 2.54 270 bottom
R225  NP  [RESCEIA0402]  119.13 66.55 90 top
R226  NP  [RESCEIA0402]  5.52 61.91 270 bottom
R227  NP  [RESCEIA0402]  88.33 15.11 90 bottom
R228  NP  [RESCEIA0402]  26.1 14.1 270 bottom
R229  NP  [RESCEIA0402]  90.35 62.1 180 bottom
R230  NP  [RESCEIA0402]  34.8 66.04 0 bottom
R231  NP  [RESCEIA0402]  19.65 58.42 90 bottom
R233  22.0  [RESCEIA0402]  93.32 39.47 270 top
R234  10K_1%  [RESCEIA0402]  86.61 26.54 90 top
R237  10K_1%  [RESCEIA0402]  79.31 21.4 0 top
R238  10K_1%  [RESCEIA0402]  77.85 17.54 180 top
R240  0.0  [RESCEIA0402]  17.27 66.01 180 bottom
R247  1K_1%  [RESCEIA0402]  26.85 60.48 0 top
R248  1K_1%  [RESCEIA0402]  7.87 61.4 180 top
R249  10K_1%  [RESCEIA0402]  25.17 62.05 270 top
R250  10K_1%  [RESCEIA0402]  9.65 61.85 270 top
R251  0.0  [RESCEIA0402]  26.35 62.04 90 top
R252  0.0  [RESCEIA0402]  7.87 60.26 180 top
R259  200_1%  [RESCEIA0402]  103 2.03 0 bottom
R260  200_1%  [RESCEIA0402]  106.11 2.03 0 bottom
R265  200_1%  [RESCEIA0402]  117.22 66.29 0 bottom
R266  200_1%  [RESCEIA0402]  117.22 65.02 0 bottom
R267  200_1%  [RESCEIA0402]  117.22 63.75 0 bottom
R268  200_1%  [RESCEIA0402]  117.22 62.48 0 bottom
R269  10K_1%  [RESCEIA0402]  29.21 37.59 180 top
R270  0.0  [RESCEIA0402]  29.21 38.73 0 top
R271  22.0  [RESCEIA0402]  46.99 43.56 0 top
R272  22.0  [RESCEIA0402]  58.93 34.54 90 top
R273  22.0  [RESCEIA0402]  60.07 34.54 90 top
R274  22.0  [RESCEIA0402]  57.78 34.54 90 top
R275  1K_1%  [RESCEIA0402]  61.21 61.37 180 top
R276  47.0K_1%  [RESCEIA0402]  62.22 57.4 180 top
R277  47.0K_1%  [RESCEIA0402]  62.22 56.26 180 top
R278  27.0K_1%  [RESCEIA0402]  62.22 55.05 0 top
R280  10K_1%  [RESCEIA0402]  50.74 52.83 0 bottom
R281  47.0K_1%  [RESCEIA0402]  65.02 48.77 180 bottom
R282  47.0K_1%  [RESCEIA0402]  62.67 54.55 270 bottom
R283  47.0K_1%  [RESCEIA0402]  65.02 48.77 180 top
R285  0.0  [RESCEIA0402]  63.31 46.61 0 bottom
R286  47.0K_1%  [RESCEIA0402]  62.22 52.83 0 top
R287  10K_1%  [RESCEIA0402]  63.88 39.94 180 bottom
R288  0.0  [RESCEIA0402]  41.78 35.24 180 top
R289  0.0  [RESCEIA0402]  41.78 38.67 180 top
R290  10K_1%  [RESCEIA0402]  64.26 41.91 0 bottom
R291  NP  [RESCEIA0402]  41.78 36.39 0 top
R292  NP  [RESCEIA0402]  41.78 37.53 0 top
R293  383K_1%  [RESCEIA0402]  64.39 44.2 90 top
R294  10K_1%  [RESCEIA0402]  61.21 60.22 0 top
R295  47.0K_1%  [RESCEIA0402]  123.89 61.4 270 bottom
R296  47.0K_1%  [RESCEIA0402]  117.22 67.56 180 bottom
R297  47.0K_1%  [RESCEIA0402]  113.16 59.88 90 bottom
R298  47.0K_1%  [RESCEIA0402]  112.01 59.88 90 bottom
R299  NP  [RESCEIA0402]  33.13 53.78 270 top
R300  NP  [RESCEIA0402]  34.28 53.78 270 top
R301  1K_1%  [RESCEIA0402]  29.02 57.91 270 top
R302  10K_1%  [RESCEIA0402]  68.17 67.77 90 top
R303  10K_1%  [RESCEIA0402]  69.29 67.77 90 top
R304  10K_1%  [RESCEIA0402]  70.41 67.77 90 top
R305  10K_1%  [RESCEIA0402]  69.6 59.75 270 bottom
R306  10K_1%  [RESCEIA0402]  70.74 53.34 180 top
R307  10K_1%  [RESCEIA0402]  66.29 51.44 180 top
R308  1K_1%  [RESCEIA0402]  10.86 4.45 180 bottom
R309  10K_1%  [RESCEIA0402]  88.58 18.29 90 bottom
R310  10K_1%  [RESCEIA0402]  111.99 49.63 270 bottom
R311  4.02K_1%  [RESCEIA0402]  90.93 38.35 0 top
R312  10K_1%  [RESCEIA0402]  107.31 57.91 0 top
R313  1.69K_1%  [RESCEIA0402]  117.09 48.9 90 bottom
R314  1.69K_1%  [RESCEIA0402]  118.24 48.9 90 bottom
R315  10K_1%  [RESCEIA0402]  119.38 48.26 270 bottom
R316  100K_1%  [RESCEIA0402]  110.11 49.02 180 bottom
R317  47.0K_1%  [RESCEIA0402]  110.11 50.16 180 bottom
R318  47.0K_1%  [RESCEIA0402]  110.11 51.31 180 bottom
R319  NP  [RESCEIA0402]  45.47 59.56 0 top
R320  NP  [RESCEIA0402]  45.47 58.29 0 top
R321  NP  [RESCEIA0402]  44.83 57.53 90 bottom
R322  NP  [RESCEIA0402]  46.1 57.53 90 bottom
R323  47.0K_1%  [RESCEIA0402]  95.76 2.92 0 bottom
R324  47.0K_1%  [RESCEIA0402]  97.41 2.67 90 bottom
R325  4.02K_1%  [RESCEIA0402]  103.33 19.25 270 top
R326  27.0K_1%  [RESCEIA0402]  93.62 2.46 0 top
R327  100K_1%  [RESCEIA0402]  92.84 18.67 180 top
R328  4.02K_1%  [RESCEIA0402]  35.43 35.75 270 top
R329  4.02K_1%  [RESCEIA0402]  34.16 38.04 0 top
RN1  22  [RESCAVS50P200X100X45-8N]  55.88 34.54 0 top
RN2  22  [RESCAVS50P200X100X45-8N]  53.34 34.54 0 top
RN3  22  [RESCAVS50P200X100X45-8N]  46.99 39.12 270 top
RN4  22  [RESCAVS50P200X100X45-8N]  46.99 41.66 270 top
RN5  22  [RESCAVS50P200X100X45-8N]  84.71 30.86 270 top
SW1  NO-POP SW DIP-1/SM  [SW_CHS-01TB]  20.65 25.91 0 top
SW2  SW DIP-4/SM  [D3-DIPSWITCH-4-HALFPITCH]  16.26 1.91 90 top
TP1  TP-LOOP-RED  [KEYSTONE_5005]  109.86 3.81 180 top
TP2  TEST-POINT RND  [D3_TP_13_RND]  25.55 34.86 0 top
TP4  TEST-POINT RND  [D3_TP_13_RND]  32.18 31.75 180 top
TP5  TEST-POINT RND  [D3_TP_13_RND]  24.45 35.5 180 top
TP6  TEST-POINT RND  [D3_TP_13_RND]  24.45 34.23 180 top
TP11  TP-LOOP-RED  [KEYSTONE_5005]  2.92 60.83 180 top
TP12  TEST-POINT  [D3_TP_15_RND]  118.24 47.24 180 top
TP13  TEST-POINT  [D3_TP_15_RND]  93.34 9.65 270 bottom
TP14  TEST-POINT RND  [D3_TP_13_RND]  90.11 27.43 180 top
TP17  TEST-POINT  [D3_TP_15_RND]  95.89 23.88 0 bottom
TP18  TEST-POINT RND  [D3_TP_13_RND]  35.43 34.1 180 top
TP19  TEST-POINT RND  [D3_TP_13_RND]  35.43 32.77 180 top
TP20  TEST-POINT RND  [D3_TP_13_RND]  37.72 32.77 180 top
TP21  TEST-POINT RND  [D3_TP_13_RND]  37.72 31.37 180 top
TP22  TEST-POINT RND  [D3_TP_13_RND]  30.1 4.06 180 top
TP23  TEST-POINT RND  [D3_TP_13_RND]  30.1 6.86 180 top
TP24  TEST-POINT RND  [D3_TP_13_RND]  30.1 5.46 180 top
TP25  TEST-POINT RND  [D3_TP_13_RND]  30.1 8.26 180 top
TP27  TP-LOOP-RED  [KEYSTONE_5005]  117.73 3.81 180 top
TP28  TEST-POINT  [D3_TP_15_RND]  99.69 18.8 180 top
TP32  TEST-POINT  [D3_TP_15_RND]  97.79 12.45 180 top
TP33  TEST-POINT  [D3_TP_15_RND]  87.38 18.8 180 top
TP34  TEST-POINT  [D3_TP_15_RND]  118.24 45.21 270 top
TP40  TEST-POINT RND  [D3_TP_13_RND]  85.41 26.04 180 top
TP44  TEST-POINT  [D3_TP_15_RND]  34.98 14.61 0 top
TP47  TEST-POINT RND  [D3_TP_13_RND]  90.81 41.02 180 top
TP48  TEST-POINT RND  [D3_TP_13_RND]  92.2 41.02 180 top
TP50  TEST-POINT  [D3_TP_15_RND]  38.23 11.56 180 top
TP51  TEST-POINT  [D3_TP_15_RND]  39.62 11.56 180 top
TP52  TEST-POINT  [D3_TP_15_RND]  36.51 1.84 180 top
TP53  TEST-POINT  [D3_TP_15_RND]  38.54 1.84 180 top
TP54  TEST-POINT  [D3_TP_15_RND]  74.24 1.85 180 top
TP55  TEST-POINT  [D3_TP_15_RND]  75.51 1.85 180 top
TP56  TEST-POINT  [D3_TP_15_RND]  76.78 1.85 180 top
TP57  TEST-POINT  [D3_TP_15_RND]  73.98 14.22 180 top
TP58  TEST-POINT  [D3_TP_15_RND]  73.98 12.83 180 top
TP59  TEST-POINT  [D3_TP_15_RND]  73.98 11.43 180 top
TP60  TEST-POINT  [D3_TP_15_RND]  76.77 11.43 180 top
TP61  TEST-POINT  [D3_TP_15_RND]  75.37 11.43 180 top
TP62  TEST-POINT  [D3_TP_15_RND]  75.37 12.83 180 top
TP63  TEST-POINT  [D3_TP_15_RND]  76.77 12.83 180 top
TP69  TEST-POINT  [D3_TP_15_RND]  96.27 12.45 180 top
TP70  TP-LOOP-BLACK  [KEYSTONE_5006]  113.67 3.81 180 top
TP72  TP-LOOP-BLACK  [KEYSTONE_5006]  1.91 8.06 90 top
TP74  TEST-POINT  [D3_TP_15_RND]  34.98 15.88 0 bottom
TP75  TEST-POINT  [D3_TP_15_RND]  40.18 15.18 0 bottom
TP76  TEST-POINT  [D3_TP_15_RND]  86.02 11.43 180 top
TP77  TEST-POINT  [D3_TP_15_RND]  87.29 11.43 180 top
TP78  TEST-POINT  [D3_TP_15_RND]  90.09 1.65 180 top
TP79  TEST-POINT  [D3_TP_15_RND]  39.94 1.84 180 top
TP80  TEST-POINT  [D3_TP_15_RND]  41.34 1.84 180 top
TP83  TP-LOOP-RED  [KEYSTONE_5005]  19.18 3.81 180 top
TP84  TEST-POINT  [D3_TP_15_RND]  45.34 43.56 270 top
TP85  TEST-POINT  [D3_TP_15_RND]  58.93 32.83 270 top
TP86  TEST-POINT  [D3_TP_15_RND]  57.53 32.83 270 top
TP87  TEST-POINT  [D3_TP_15_RND]  60.33 32.83 270 top
TP88  TEST-POINT  [D3_TP_15_RND]  68.94 57.58 0 top
TP89  TEST-POINT  [D3_TP_15_RND]  67.67 57.58 0 top
U1  TPS54341DPRT  [SON80P400X400X80-11N_ALT]  108.84 17.59 180 top
U3  TPS1H100-Q1  [SOP65P640X120-15N_ALT]  12.95 61.59 0 bottom
U4  TPS61240  [SON65P200X200X80-7N]  113.03 47.12 180 top
U5  TPS62090RGTT  [QFN50P300X300X100-17N_ALT]  96.9 5.21 0 top
U6  DS90UB964-Q1  [QFN50P900X900X100-65N_ALT1]  33.66 25.35 270 bottom
U7  25.000MHz  [OSC250X200X85-4N]  31.6 38 270 bottom
U9  DP83867CRRGZT  [QFN50P700X700X100-49N_ALT2]  90.81 33.38 180 top
U10  HVDA551-Q1  [SOIC127P600X175-8N]  99.82 65.6 0 top
U13  TPS62170  [SON50P200X200X80-9N]  92.27 20.57 0 top
U14  25.000MHz  [OSC250X200X85-4N]  95.39 40.77 180 top
U16  TFP410  [QFP50P1200X1200X100-65N]  97.5 51.43 90 top
U20  TPD12S521  [SOP50P640X120-38N]  112.78 54.16 0 top
U21  TPS22965DSGT  [SON50P200X200X80-9N]  37.26 14.35 0 top
U22  TCA9539PW  [SOP65P640X120-24N]  25.15 6.35 180 top
U28  TMP102  [SOTFL50P160X60-6N]  41.66 41.4 0 bottom
U38  SN74AVC4T245RGY  [QFN50P400X350X100-21_16N]  34.54 48.7 180 bottom
U41  SN74LVC2G34DCKR  [SOT65P210X110-6N]  122.81 61.09 180 top
U42  SN74LVC2G34DCKR  [SOT65P210X110-6N]  118.55 60.01 90 bottom
U43  TPD12S520  [SOP50P640X120-38N]  56 55.75 90 top
U44  ADV7611  [QFP50P1200X1200X160-65N]  55.5 43.18 270 top
U45  CAT24C08  [SOP65P640X120-8N]  68.96 62.36 270 top
U46  SN74CB3Q3257  [SOP65P640X120-16N]  67.94 54.36 0 bottom
U47  CP2102N  [USB_SILICON_LABS_CP2102N]  32.38 57.15 270 top
U48  SN74CB3Q3345  [QFN50P450X350X100-25_20N]  81.79 18.29 0 top
U49  TPD2E001  [SOTFL50P160X60-5N]  27.48 62.33 0 bottom
Y2  28.6363MHz  [XTAL500X320X130]  67.94 44.2 90 top

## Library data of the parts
C1-C3 C5-C7 C20-C63 C65-C92 C107-C111 C123-C132 C135-C137 C140-C146 C150-C153 C155-C168 C175-C184 C186 C187 C191-C194 C207 C208 C213 C217 C218 C220-C224 C229-C232 C235-C243 C246-C248 C250-C267 = C_NP
D1 D23 = SCHOTTKY_2AC
D8 D9 = TVS1_2
D12 D17 D18 = LED_AC
D21 = ZENER_AC
J6-J9 = D3_SMB_2
J13 = SAMTEC_QSH-030
J14 = SAMTEC_QTH-090
J19 J26 = HDMI-MINI-TYPE-C
J21 = D3-MICROSD-1
J23 = MINIUSB_B
J24 = JK0-0136NL
J25 = BARREL_JACK
J27 = HEADER 8X2
J28 = D3_CONN_4X2
J29 = D3_CONN_3
L1-L18 L21-L28 L36-L38 L40-L43 L47-L51 = INDUCTOR
L19 L20 L29 L30 = CM_CHOKE_2
LR1-LR8 R8 R10 R12-R14 R24-R26 R28 R30 R31 R33-R46 R51 R53 R58-R61 R63-R78 R89-R93 R101 R102 R104 R105 R107-R112 R117-R121 R125 R130-R139 R145-R158 R166 R172 R174 R179-R197 R199-R207 R222-R231 R233 R234 R237 R238 R240 R247-R252 R259 R260 R265-R278 R280-R283 R285-R329 = RESISTOR
MH1-MH4 = MOUNT_HOLE_1
MH5-MH8 = STANDOFF_MOUNT_HOLE_1
Q7 Q8 = MOSFET_N_1
RN1-RN5 = R_4PACK_ISO_2
SW1 = SW DIP-1
SW2 = SW DIP-4
TP1 TP2 TP4-TP6 TP11-TP14 TP17-TP25 TP27 TP28 TP32-TP34 TP40 TP44 TP47 TP48 TP50-TP63 TP69 TP70 TP72 TP74-TP80 TP83-TP89 = TEST-POINT-1
U1 = TPS54361
U3 = TPS1H100
U4 = TPS61240
U5 = TPS62090
U6 = DS90UB960
U7 U14 = OSC_4PIN_1
U9 = DP83867
U10 = SN65HVDA54X_0
U13 = TPS6217x
U16 = TFP410
U20 = TPD12S521_1
U21 = TPS22965DSG
U22 = TCA9539PW
U28 = TMP102AIDRL
U38 = SN74AVC4T245RGY
U41 U42 = BUFFER_DUAL_2
U43 = TPD12S520
U44 = ADV7611
U45 = CAT24C02
U46 = SN74CB3T3125
U47 = CP2102N
U48 = SN74CB3Q3345RGY
U49 = TPDE0001RSE
Y2 = CRYSTAL_2PIN

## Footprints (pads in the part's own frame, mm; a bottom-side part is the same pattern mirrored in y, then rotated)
CAPCEIA0402
  rect 0.63x0.73 smd: 1(-0.51,0) 2(0.51,0)
CAPCEIA0603
  rect 0.9x1 smd: 1(-0.8,0) 2(0.8,0)
CAPCEIA0805
  rect 1.2x1.45 smd: 1(-0.85,0) 2(0.85,0)
CAPCEIA1206
  rect 1.2x1.75 smd: 1(-1.5,0) 2(1.5,0)
CAPCEIA1210
  rect 1.15x2.7 smd: 1(-1.5,0) 2(1.5,0)
D3-DIPSWITCH-4-HALFPITCH
  rect 0.762x1.27 smd: 1(0,0)
  oval 0.762x1.27 smd: 2(1.27,0) 3(2.54,0) 4(3.81,0) 5(3.81,7.62) 6(2.54,7.62) 7(1.27,7.62) 8(0,7.62)
D3-ST_HEADER_8X2_100
  rect 1.778x1.778 hole 1.016: 1(0,0)
  round 1.778 hole 1.016: 2(0,2.54) 3(2.54,0) 4(2.54,2.54) 5(5.08,0) 6(5.08,2.54) 7(7.62,0) 8(7.62,2.54) 9(10.16,0) 10(10.16,2.54) 11(12.7,0) 12(12.7,2.54) 13(15.24,0) 14(15.24,2.54) 15(17.78,0) 16(17.78,2.54)
D3_TP_13_RND
  round 0.66 hole 0.33: 1(0,0)
D3_TP_15_RND
  round 0.71 hole 0.38: 1(0,0)
DFN528X548X510-2N
  rect 1.18x4.7 smd: 1(-1.655,0) 2(1.655,0)
DIO_DIODES_PDS760Q
  rect 1.39x1.4 smd: A1(-0.92,-2.856) A2(0.92,-2.856)
  rect 3.36x4.86 smd: C(0,1.126)
HIROSE_ZX62D-B-5P8
  rect 1.8x1.9 smd: (0.15,-2.675) (2.45,-2.675)
  rect 0.4x1.35 smd: 1(0,0) 2(0.65,0) 3(1.3,0) 4(1.95,0) 5(2.6,0)
  oval 1.05x1.25 hole 0.65x0.85: 6(-1.125,0.325) 7(3.725,0.325)
  custom 0.475x0.475 hole 1.5x0.83: 8(-2.35,-2.675) 9(4.95,-2.675)
IND_COILCRAFT_MSS7341T
  custom 0.625x0.625 smd: 1(-3.187,0) 2(3.187,0)
IND_COILCRAFT_XPL2010
  rect 1.04x2.2 smd: 1(-0.725,0) 2(0.725,0)
IND_MURATA_DLW21SN900HQ2L
  rect 0.9x0.4 smd: 1(-0.85,-0.4) 2(0.85,-0.4) 3(0.85,0.4) 4(-0.85,0.4)
IND_WURTH_WE-TPC-4818
  custom 0.5x0.5 smd: 1(-2.275,0) 2(2.275,0)
INDC2016X180N
  rect 1.15x1.8 smd: 1(-0.9,0) 2(0.9,0)
INDCEIA0603
  rect 0.9x1 smd: 1(-0.8,0) 2(0.8,0)
JACK_PULSE_JK0-0136NL
  round 1 hole 3.2 unplated: (-15.24,6.35) (-15.24,-6.35)
  rect 1.4x1.4 hole 0.9: 1(0,-5.075)
  round 1.4 hole 0.9: 2(0,-3.045) 3(0,-1.015) 4(0,1.015) 5(0,3.045) 6(0,5.075) 7(2.54,-6.095) 8(2.54,-4.065) 9(2.54,-2.035) 10(2.54,2.035) 11(2.54,4.065) 12(2.54,6.095)
  round 1.6 hole 1.05: 13(5.08,-6.095) 14(5.08,-3.555) 15(5.08,3.555) 16(5.08,6.095)
  round 2.4 hole 1.6: 17(-18.42,8.065) 18(-18.42,-8.065)
KEYSTONE_5005
  round 2.35 hole 1.85: 1(0,0)
KEYSTONE_5006
  round 2.35 hole 1.85: 1(0,0)
LEDC1608X65N
  rect 0.6x0.8 smd: A(0.725,0) C(-0.725,0)
MOLEX_22-28-4033
  rect 1.778x1.778 hole 1.016: 1(0,0)
  round 1.778 hole 1.016: 2(2.54,0) 3(5.08,0)
MOLEX_5031821853
  rect 1.15x2.5 smd: (-4.245,-0.63)
  rect 1.15x2.2 smd: (-4.245,-11.96) (10.045,-0.48)
  rect 1.5x1.15 smd: (0.06,-12.755) (7.84,-12.755)
  rect 0.8x1.24 smd: 1(0,0) 2(1.1,0) 3(2.2,0) 4(3.3,0) 5(4.4,0) 6(5.5,0) 7(6.6,0) 8(7.7,0)
  rect 1.16x1.2 smd: 9(9.64,-11.63)
  rect 1.16x1.25 smd: 10(9.64,-2.63)
MTG340_610
  round 6.1 hole 3.4: 1(0,0)
OSC250X200X85-4N
  rect 0.65x0.85 smd: 1(-0.825,-0.775) 2(0.825,-0.775) 3(0.825,0.775) 4(-0.825,0.775)
PENN_SMTSO-M2-8ET
  round 6.2 hole 3.73: 1(0,0)
QFN50P300X300X100-17N_ALT
  oval 0.8x0.3 smd: 1(-1.5,0.75) 2(-1.5,0.25) 3(-1.5,-0.25) 4(-1.5,-0.75) 9(1.5,-0.75) 10(1.5,-0.25) 11(1.5,0.25) 12(1.5,0.75)
  oval 0.3x0.8 smd: 5(-0.75,-1.5) 6(-0.25,-1.5) 7(0.25,-1.5) 8(0.75,-1.5) 13(0.75,1.5) 14(0.25,1.5) 15(-0.25,1.5) 16(-0.75,1.5)
  rect 1.8x1.8 smd: 17(0,0)
QFN50P400X350X100-21_16N
  custom 0.07x0.07 smd: 1(-1.975,-0.75) 2(-1.25,-1.725) 3(-0.75,-1.725) 4(-0.25,-1.725) 5(0.25,-1.725) 6(0.75,-1.725) 7(1.25,-1.725) 8(1.975,-0.75) 9(1.975,0.75) 10(1.25,1.725) 11(0.75,1.725) 12(0.25,1.725) 13(-0.25,1.725) 14(-0.75,1.725) 15(-1.25,1.725) 16(-1.975,0.75)
  rect 2.55x2.05 smd: 17(0,0)
QFN50P450X350X100-25_20N
  custom 0.07x0.07 smd: 1(-2.225,-0.75) 2(-1.75,-1.725) 3(-1.25,-1.725) 4(-0.75,-1.725) 5(-0.25,-1.725) 6(0.25,-1.725) 7(0.75,-1.725) 8(1.25,-1.725) 9(1.75,-1.725) 10(2.225,-0.75) 11(2.225,0.75) 12(1.75,1.725) 13(1.25,1.725) 14(0.75,1.725) 15(0.25,1.725) 16(-0.25,1.725) 17(-0.75,1.725) 18(-1.25,1.725) 19(-1.75,1.725) 20(-2.225,0.75)
  rect 3.05x2.05 smd: 21(0,0)
QFN50P700X700X100-49N_ALT2
  oval 0.9x0.3 smd: 1(-3.45,2.75) 2(-3.45,2.25) 3(-3.45,1.75) 4(-3.45,1.25) 5(-3.45,0.75) 6(-3.45,0.25) 7(-3.45,-0.25) 8(-3.45,-0.75) 9(-3.45,-1.25) 10(-3.45,-1.75) 11(-3.45,-2.25) 12(-3.45,-2.75) 25(3.45,-2.75) 26(3.45,-2.25) 27(3.45,-1.75) 28(3.45,-1.25) 29(3.45,-0.75) 30(3.45,-0.25) 31(3.45,0.25) 32(3.45,0.75) 33(3.45,1.25) 34(3.45,1.75) 35(3.45,2.25) 36(3.45,2.75)
  oval 0.3x0.9 smd: 13(-2.75,-3.45) 14(-2.25,-3.45) 15(-1.75,-3.45) 16(-1.25,-3.45) 17(-0.75,-3.45) 18(-0.25,-3.45) 19(0.25,-3.45) 20(0.75,-3.45) 21(1.25,-3.45) 22(1.75,-3.45) 23(2.25,-3.45) 24(2.75,-3.45) 37(2.75,3.45) 38(2.25,3.45) 39(1.75,3.45) 40(1.25,3.45) 41(0.75,3.45) 42(0.25,3.45) 43(-0.25,3.45) 44(-0.75,3.45) 45(-1.25,3.45) 46(-1.75,3.45) 47(-2.25,3.45) 48(-2.75,3.45)
  rect 4.15x4.15 smd: 49(0,0)
QFN50P900X900X100-65N_ALT1
  oval 0.9x0.3 smd: 1(-4.45,3.75) 2(-4.45,3.25) 3(-4.45,2.75) 4(-4.45,2.25) 5(-4.45,1.75) 6(-4.45,1.25) 7(-4.45,0.75) 8(-4.45,0.25) 9(-4.45,-0.25) 10(-4.45,-0.75) 11(-4.45,-1.25) 12(-4.45,-1.75) 13(-4.45,-2.25) 14(-4.45,-2.75) 15(-4.45,-3.25) 16(-4.45,-3.75) 33(4.45,-3.75) 34(4.45,-3.25) 35(4.45,-2.75) 36(4.45,-2.25) 37(4.45,-1.75) 38(4.45,-1.25) 39(4.45,-0.75) 40(4.45,-0.25) 41(4.45,0.25) 42(4.45,0.75) 43(4.45,1.25) 44(4.45,1.75) 45(4.45,2.25) 46(4.45,2.75) 47(4.45,3.25) 48(4.45,3.75)
  oval 0.3x0.9 smd: 17(-3.75,-4.45) 18(-3.25,-4.45) 19(-2.75,-4.45) 20(-2.25,-4.45) 21(-1.75,-4.45) 22(-1.25,-4.45) 23(-0.75,-4.45) 24(-0.25,-4.45) 25(0.25,-4.45) 26(0.75,-4.45) 27(1.25,-4.45) 28(1.75,-4.45) 29(2.25,-4.45) 30(2.75,-4.45) 31(3.25,-4.45) 32(3.75,-4.45) 49(3.75,4.45) 50(3.25,4.45) 51(2.75,4.45) 52(2.25,4.45) 53(1.75,4.45) 54(1.25,4.45) 55(0.75,4.45) 56(0.25,4.45) 57(-0.25,4.45) 58(-0.75,4.45) 59(-1.25,4.45) 60(-1.75,4.45) 61(-2.25,4.45) 62(-2.75,4.45) 63(-3.25,4.45) 64(-3.75,4.45)
  custom 1.5x1.5 smd: 65(0,0)
QFP50P1200X1200X100-65N
  rect 1.5x0.3 smd: 1(-5.75,3.75) 2(-5.75,3.25) 3(-5.75,2.75) 4(-5.75,2.25) 5(-5.75,1.75) 6(-5.75,1.25) 7(-5.75,0.75) 8(-5.75,0.25) 9(-5.75,-0.25) 10(-5.75,-0.75) 11(-5.75,-1.25) 12(-5.75,-1.75) 13(-5.75,-2.25) 14(-5.75,-2.75) 15(-5.75,-3.25) 16(-5.75,-3.75) 33(5.75,-3.75) 34(5.75,-3.25) 35(5.75,-2.75) 36(5.75,-2.25) 37(5.75,-1.75) 38(5.75,-1.25) 39(5.75,-0.75) 40(5.75,-0.25) 41(5.75,0.25) 42(5.75,0.75) 43(5.75,1.25) 44(5.75,1.75) 45(5.75,2.25) 46(5.75,2.75) 47(5.75,3.25) 48(5.75,3.75)
  rect 0.3x1.5 smd: 17(-3.75,-5.75) 18(-3.25,-5.75) 19(-2.75,-5.75) 20(-2.25,-5.75) 21(-1.75,-5.75) 22(-1.25,-5.75) 23(-0.75,-5.75) 24(-0.25,-5.75) 25(0.25,-5.75) 26(0.75,-5.75) 27(1.25,-5.75) 28(1.75,-5.75) 29(2.25,-5.75) 30(2.75,-5.75) 31(3.25,-5.75) 32(3.75,-5.75) 49(3.75,5.75) 50(3.25,5.75) 51(2.75,5.75) 52(2.25,5.75) 53(1.75,5.75) 54(1.25,5.75) 55(0.75,5.75) 56(0.25,5.75) 57(-0.25,5.75) 58(-0.75,5.75) 59(-1.25,5.75) 60(-1.75,5.75) 61(-2.25,5.75) 62(-2.75,5.75) 63(-3.25,5.75) 64(-3.75,5.75)
  rect 8x8 smd: 65(0,0)
QFP50P1200X1200X160-65N
  rect 1.5x0.3 smd: 1(-5.7,3.75) 2(-5.7,3.25) 3(-5.7,2.75) 4(-5.7,2.25) 5(-5.7,1.75) 6(-5.7,1.25) 7(-5.7,0.75) 8(-5.7,0.25) 9(-5.7,-0.25) 10(-5.7,-0.75) 11(-5.7,-1.25) 12(-5.7,-1.75) 13(-5.7,-2.25) 14(-5.7,-2.75) 15(-5.7,-3.25) 16(-5.7,-3.75) 33(5.7,-3.75) 34(5.7,-3.25) 35(5.7,-2.75) 36(5.7,-2.25) 37(5.7,-1.75) 38(5.7,-1.25) 39(5.7,-0.75) 40(5.7,-0.25) 41(5.7,0.25) 42(5.7,0.75) 43(5.7,1.25) 44(5.7,1.75) 45(5.7,2.25) 46(5.7,2.75) 47(5.7,3.25) 48(5.7,3.75)
  rect 0.3x1.5 smd: 17(-3.75,-5.7) 18(-3.25,-5.7) 19(-2.75,-5.7) 20(-2.25,-5.7) 21(-1.75,-5.7) 22(-1.25,-5.7) 23(-0.75,-5.7) 24(-0.25,-5.7) 25(0.25,-5.7) 26(0.75,-5.7) 27(1.25,-5.7) 28(1.75,-5.7) 29(2.25,-5.7) 30(2.75,-5.7) 31(3.25,-5.7) 32(3.75,-5.7) 49(3.75,5.7) 50(3.25,5.7) 51(2.75,5.7) 52(2.25,5.7) 53(1.75,5.7) 54(1.25,5.7) 55(0.75,5.7) 56(0.25,5.7) 57(-0.25,5.7) 58(-0.75,5.7) 59(-1.25,5.7) 60(-1.75,5.7) 61(-2.25,5.7) 62(-2.75,5.7) 63(-3.25,5.7) 64(-3.75,5.7)
  rect 5x5 smd: 65(0,0)
RESCAVS50P200X100X45-8N
  rect 0.4x0.5 smd: 1(-0.8,-0.475) 4(0.8,-0.475) 5(0.8,0.475) 8(-0.8,0.475)
  rect 0.3x0.5 smd: 2(-0.25,-0.475) 3(0.25,-0.475) 6(0.25,0.475) 7(-0.25,0.475)
RESCEIA0402
  rect 0.63x0.73 smd: 1(-0.51,0) 2(0.51,0)
RESCEIA0603
  rect 0.9x1 smd: 1(-0.8,0) 2(0.8,0)
ROSENBERGER_59S2AQ-40MT5-Y_1
  custom 0.6x0.6 hole 1.6: 1(-3,3.5) 2(3,3.5) 3(3,-3.5) 4(-3,-3.5)
  rect 1.9x3.15 smd: 5(0,-3.971)
SAMTEC_QSH-030-01-L-D-A-K
  round 0.5 hole 1.05 unplated: (-2.815,5.54) (17.315,5.54)
  rect 0.28x2.27 smd: 1(0,0) 2(0,5.74) 3(0.5,0) 4(0.5,5.74) 5(1,0) 6(1,5.74) 7(1.5,0) 8(1.5,5.74) 9(2,0) 10(2,5.74) 11(2.5,0) 12(2.5,5.74) 13(3,0) 14(3,5.74) 15(3.5,0) 16(3.5,5.74) 17(4,0) 18(4,5.74) 19(4.5,0) 20(4.5,5.74) 21(5,0) 22(5,5.74) 23(5.5,0) 24(5.5,5.74) 25(6,0) 26(6,5.74) 27(6.5,0) 28(6.5,5.74) 29(7,0) 30(7,5.74) 31(7.5,0) 32(7.5,5.74) 33(8,0) 34(8,5.74) 35(8.5,0) 36(8.5,5.74) 37(9,0) 38(9,5.74) 39(9.5,0) 40(9.5,5.74) 41(10,0) 42(10,5.74) 43(10.5,0) 44(10.5,5.74) 45(11,0) 46(11,5.74) 47(11.5,0) 48(11.5,5.74) 49(12,0) 50(12,5.74) 51(12.5,0) 52(12.5,5.74) 53(13,0) 54(13,5.74) 55(13.5,0) 56(13.5,5.74) 57(14,0) 58(14,5.74) 59(14.5,0) 60(14.5,5.74)
  rect 2.54x0.43 smd: 61(-0.81,2.87) 64(15.31,2.87)
  rect 4.7x0.43 smd: 62(4.08,2.87) 63(10.42,2.87)
SAMTEC_QTH-090-02-L-D-A-K
  round 0.5 hole 1.05 unplated: (-1.987,-1.05) (56.493,-1.05)
  rect 0.3x1.45 smd: 1(0,0) 2(0,-6.172) 3(0.5,0) 4(0.5,-6.172) 5(1,0) 6(1,-6.172) 7(1.5,0) 8(1.5,-6.172) 9(2,0) 10(2,-6.172) 11(2.5,0) 12(2.5,-6.172) 13(3,0) 14(3,-6.172) 15(3.5,0) 16(3.5,-6.172) 17(4,0) 18(4,-6.172) 19(4.5,0) 20(4.5,-6.172) 21(5,0) 22(5,-6.172) 23(5.5,0) 24(5.5,-6.172) 25(6,0) 26(6,-6.172) 27(6.5,0) 28(6.5,-6.172) 29(7,0) 30(7,-6.172) 31(7.5,0) 32(7.5,-6.172) 33(8,0) 34(8,-6.172) 35(8.5,0) 36(8.5,-6.172) 37(9,0) 38(9,-6.172) 39(9.5,0) 40(9.5,-6.172) 41(10,0) 42(10,-6.172) 43(10.5,0) 44(10.5,-6.172) 45(11,0) 46(11,-6.172) 47(11.5,0) 48(11.5,-6.172) 49(12,0) 50(12,-6.172) 51(12.5,0) 52(12.5,-6.172) 53(13,0) 54(13,-6.172) 55(13.5,0) 56(13.5,-6.172) 57(14,0) 58(14,-6.172) 59(14.5,0) 60(14.5,-6.172) 61(20.003,0) 62(20.003,-6.172) 63(20.503,0) 64(20.503,-6.172) 65(21.003,0) 66(21.003,-6.172) 67(21.503,0) 68(21.503,-6.172) 69(22.003,0) 70(22.003,-6.172) 71(22.503,0) 72(22.503,-6.172) 73(23.003,0) 74(23.003,-6.172) 75(23.503,0) 76(23.503,-6.172) 77(24.003,0) 78(24.003,-6.172) 79(24.503,0) 80(24.503,-6.172) 81(25.003,0) 82(25.003,-6.172) 83(25.503,0) 84(25.503,-6.172) 85(26.003,0) 86(26.003,-6.172) 87(26.503,0) 88(26.503,-6.172) 89(27.003,0) 90(27.003,-6.172) 91(27.503,0) 92(27.503,-6.172) 93(28.003,0) 94(28.003,-6.172) 95(28.503,0) 96(28.503,-6.172) 97(29.003,0) 98(29.003,-6.172) 99(29.503,0) 100(29.503,-6.172) 101(30.003,0) 102(30.003,-6.172) 103(30.503,0) 104(30.503,-6.172) 105(31.003,0) 106(31.003,-6.172) 107(31.503,0) 108(31.503,-6.172) 109(32.003,0) 110(32.003,-6.172) 111(32.503,0) 112(32.503,-6.172) 113(33.003,0) 114(33.003,-6.172) 115(33.503,0) 116(33.503,-6.172) 117(34.003,0) 118(34.003,-6.172) 119(34.503,0) 120(34.503,-6.172) 121(40.006,0) 122(40.006,-6.172) 123(40.506,0) 124(40.506,-6.172) 125(41.006,0) 126(41.006,-6.172) 127(41.506,0) 128(41.506,-6.172) 129(42.006,0) 130(42.006,-6.172) 131(42.506,0) 132(42.506,-6.172) 133(43.006,0) 134(43.006,-6.172) 135(43.506,0) 136(43.506,-6.172) 137(44.006,0) 138(44.006,-6.172) 139(44.506,0) 140(44.506,-6.172) 141(45.006,0) 142(45.006,-6.172) 143(45.506,0) 144(45.506,-6.172) 145(46.006,0) 146(46.006,-6.172) 147(46.506,0) 148(46.506,-6.172) 149(47.006,0) 150(47.006,-6.172) 151(47.506,0) 152(47.506,-6.172) 153(48.006,0) 154(48.006,-6.172) 155(48.506,0) 156(48.506,-6.172) 157(49.006,0) 158(49.006,-6.172) 159(49.506,0) 160(49.506,-6.172) 161(50.006,0) 162(50.006,-6.172) 163(50.506,0) 164(50.506,-6.172) 165(51.006,0) 166(51.006,-6.172) 167(51.506,0) 168(51.506,-6.172) 169(52.006,0) 170(52.006,-6.172) 171(52.506,0) 172(52.506,-6.172) 173(53.006,0) 174(53.006,-6.172) 175(53.506,0) 176(53.506,-6.172) 177(54.006,0) 178(54.006,-6.172) 179(54.506,0) 180(54.506,-6.172)
  rect 2.54x0.64 smd: 181(-1.195,-3.086) 184(15.695,-3.086) 185(18.808,-3.086) 188(35.698,-3.086) 189(38.811,-3.086) 192(55.701,-3.086)
  rect 4.7x0.64 smd: 182(4.075,-3.086) 183(10.425,-3.086) 186(24.078,-3.086) 187(30.428,-3.086) 190(44.081,-3.086) 191(50.431,-3.086)
SAMTEC_TFC-104-01-F-D-A
  round 1 hole 1.4 unplated: (-1.59,0.635) (5.4,0.635)
  rect 1x1 hole 0.65: 1(0,0)
  round 1 hole 0.65: 2(0,1.27) 3(1.27,0) 4(1.27,1.27) 5(2.54,0) 6(2.54,1.27) 7(3.81,0) 8(3.81,1.27)
SOD3716X135N
  rect 1x0.8 smd: A(1.8,0) C(-1.8,0)
SOIC127P600X175-8N
  rect 1.55x0.6 smd: 1(-2.7,1.905) 2(-2.7,0.635) 3(-2.7,-0.635) 4(-2.7,-1.905) 5(2.7,-1.905) 6(2.7,-0.635) 7(2.7,0.635) 8(2.7,1.905)
SON50P200X200X80-9N
  rect 0.7x0.3 smd: 1(-1.05,0.75) 2(-1.05,0.25) 3(-1.05,-0.25) 4(-1.05,-0.75) 5(1.05,-0.75) 6(1.05,-0.25) 7(1.05,0.25) 8(1.05,0.75)
  rect 0.9x1.6 smd: 9(0,0)
SON65P200X200X80-7N
  rect 0.65x0.35 smd: 1(-1.05,0.65) 2(-1.05,0) 3(-1.05,-0.65) 4(1.05,-0.65) 5(1.05,0) 6(1.05,0.65)
  custom 0.25x0.25 smd: 7(0,0)
SON80P400X400X80-11N_ALT
  oval 0.85x0.35 smd: 1(-1.95,1.6) 2(-1.95,0.8) 3(-1.95,0) 4(-1.95,-0.8) 5(-1.95,-1.6) 6(1.95,-1.6) 7(1.95,-0.8) 8(1.95,0) 9(1.95,0.8) 10(1.95,1.6)
  rect 2.6x3 smd: 11(0,0)
SOP50P640X120-38N
  rect 1.5x0.3 smd: 1(-2.9,4.5) 2(-2.9,4) 3(-2.9,3.5) 4(-2.9,3) 5(-2.9,2.5) 6(-2.9,2) 7(-2.9,1.5) 8(-2.9,1) 9(-2.9,0.5) 10(-2.9,0) 11(-2.9,-0.5) 12(-2.9,-1) 13(-2.9,-1.5) 14(-2.9,-2) 15(-2.9,-2.5) 16(-2.9,-3) 17(-2.9,-3.5) 18(-2.9,-4) 19(-2.9,-4.5) 20(2.9,-4.5) 21(2.9,-4) 22(2.9,-3.5) 23(2.9,-3) 24(2.9,-2.5) 25(2.9,-2) 26(2.9,-1.5) 27(2.9,-1) 28(2.9,-0.5) 29(2.9,0) 30(2.9,0.5) 31(2.9,1) 32(2.9,1.5) 33(2.9,2) 34(2.9,2.5) 35(2.9,3) 36(2.9,3.5) 37(2.9,4) 38(2.9,4.5)
SOP65P640X120-8N
  rect 1.5x0.45 smd: 1(-2.9,0.975) 2(-2.9,0.325) 3(-2.9,-0.325) 4(-2.9,-0.975) 5(2.9,-0.975) 6(2.9,-0.325) 7(2.9,0.325) 8(2.9,0.975)
SOP65P640X120-15N_ALT
  rect 1.5x0.45 smd: 1(-2.9,1.95) 2(-2.9,1.3) 3(-2.9,0.65) 4(-2.9,0) 5(-2.9,-0.65) 6(-2.9,-1.3) 7(-2.9,-1.95) 8(2.9,-1.95) 9(2.9,-1.3) 10(2.9,-0.65) 11(2.9,0) 12(2.9,0.65) 13(2.9,1.3) 14(2.9,1.95)
  rect 2.3x2.45 smd: 15(0,0)
SOP65P640X120-16N
  rect 1.5x0.45 smd: 1(-2.9,2.275) 2(-2.9,1.625) 3(-2.9,0.975) 4(-2.9,0.325) 5(-2.9,-0.325) 6(-2.9,-0.975) 7(-2.9,-1.625) 8(-2.9,-2.275) 9(2.9,-2.275) 10(2.9,-1.625) 11(2.9,-0.975) 12(2.9,-0.325) 13(2.9,0.325) 14(2.9,0.975) 15(2.9,1.625) 16(2.9,2.275)
SOP65P640X120-24N
  rect 1.5x0.45 smd: 1(-2.9,3.575) 2(-2.9,2.925) 3(-2.9,2.275) 4(-2.9,1.625) 5(-2.9,0.975) 6(-2.9,0.325) 7(-2.9,-0.325) 8(-2.9,-0.975) 9(-2.9,-1.625) 10(-2.9,-2.275) 11(-2.9,-2.925) 12(-2.9,-3.575) 13(2.9,-3.575) 14(2.9,-2.925) 15(2.9,-2.275) 16(2.9,-1.625) 17(2.9,-0.975) 18(2.9,-0.325) 19(2.9,0.325) 20(2.9,0.975) 21(2.9,1.625) 22(2.9,2.275) 23(2.9,2.925) 24(2.9,3.575)
SOT65P210X110-6N
  rect 1x0.4 smd: 1(-1.1,0.65) 2(-1.1,0) 3(-1.1,-0.65) 4(1.1,-0.65) 5(1.1,0) 6(1.1,0.65)
SOT95P237X111-3N
  rect 1.05x0.6 smd: 1(-1.15,0.95) 2(-1.15,-0.95) 3(1.15,0)
SOTFL50P160X60-5N
  rect 0.57x0.3 smd: 1(-0.79,0.5) 2(-0.79,0) 3(-0.79,-0.5) 4(0.79,-0.5) 5(0.79,0.5)
SOTFL50P160X60-6N
  rect 0.67x0.3 smd: 1(-0.74,0.5) 2(-0.74,0) 3(-0.74,-0.5) 4(0.74,-0.5) 5(0.74,0) 6(0.74,0.5)
SW_CHS-01TB
  rect 1x1.6 smd: 1(0,-2.54) 2(0,2.54)
unnamed#2
  round 1 smd: (0,0)
USB_SILICON_LABS_CP2102N
  rect 0.3x0.3 smd: 1(-1.25,1.25) 6(-1.25,-1.25) 11(1.25,-1.25) 16(1.25,1.25)
  rect 0.9x0.3 smd: 2(-1.55,0.75) 3(-1.55,0.25) 4(-1.55,-0.25) 5(-1.55,-0.75) 12(1.55,-0.75) 13(1.55,-0.25) 14(1.55,0.25) 15(1.55,0.75)
  rect 0.3x0.9 smd: 7(-0.75,-1.55) 8(-0.25,-1.55) 9(0.25,-1.55) 10(0.75,-1.55) 17(0.75,1.55) 18(0.25,1.55) 19(-0.25,1.55) 20(-0.75,1.55)
  rect 1.8x1.8 smd: 21(0,0)
WURTH_685119136923
  rect 0.23x1 smd: 1(0,0) 2(0.4,0) 3(0.8,0) 4(1.2,0) 5(1.6,0) 6(2,0) 7(2.4,0) 8(2.8,0) 9(3.2,0) 10(3.6,0) 11(4,0) 12(4.4,0) 13(4.8,0) 14(5.2,0) 15(5.6,0) 16(6,0) 17(6.4,0) 18(6.8,0) 19(7.2,0)
  oval 1.2x1.9 hole 0.6x1.3: 20(-1.825,1.05) 21(9.025,1.05)
  oval 1.2x1.7 hole 0.6x1.1: 22(-1.825,5.55) 23(9.025,5.55)
WURTH_694106301002
  rect 1.3x3.5 hole 0.8x3: 1(0,0) 2(-5.8,0)
  rect 3.5x1.3 hole 3x0.8: 3(-3,-4.8)
XTAL500X320X130
  rect 1.9x2.4 smd: 1(-2.05,0) 2(2.05,0)

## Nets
